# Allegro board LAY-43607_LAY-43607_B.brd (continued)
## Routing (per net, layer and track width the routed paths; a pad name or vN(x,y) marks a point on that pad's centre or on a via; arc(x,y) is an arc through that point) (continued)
IFC_AD6: length 65.4
  TOP w0.137: v2(84.82,50.41) 84.4,50.41 84.3,50.32 83.13,50.32 82.76,49.95 79.47,49.95 78.36,48.84 76.52,48.84 75.87,48.2 U14.A11
  L3_INT_1 w0.107: v2(84.82,50.41) 85.38,50.97 94.95,50.97 96.51,49.42 99.02,49.42 101.88,46.56 101.88,45.9 102.91,44.87 102.91,44.87 105.75,42.03 105.75,40.71 106.15,40.31 106.15,40.16 105.72,39.72 105.72,39.57 105.87,39.42 106.02,39.42 106.46,39.86 106.61,39.86 106.76,39.71 106.76,39.55 106.32,39.12 106.32,38.97 106.47,38.82 106.62,38.82 107.06,39.25 107.21,39.25 107.36,39.1 107.36,38.95 106.92,38.52 106.92,38.36 107.08,38.21 107.23,38.21 107.66,38.65 107.81,38.65 107.96,38.5 107.96,38.35 107.53,37.91 107.53,37.76 107.68,37.61 107.83,37.61 108.27,38.05 108.42,38.05 109.15,37.31 109.15,33.79 109.26,33.68 109.54,33.68 109.64,33.58 109.64,33.36 109.54,33.26 109.26,33.26 109.15,33.15 v2(109.15,32.34)
  BOTTOM w0.137: U522.J4 111.58,24.85 111.58,25.14 111.48,25.24 111.48,25.53 111.61,25.66 111.61,26.18 111.47,26.32 111.11,26.32 110.98,26.45 110.98,26.73 111.11,26.87 111.47,26.87 111.61,27 111.61,27.42 111.47,27.56 111.01,27.56 110.88,27.7 110.88,27.97 111.01,28.11 111.47,28.11 111.61,28.24 111.61,28.81 110.26,30.16 110.06,30.16 109.67,29.76 109.48,29.76 109.28,29.96 109.28,30.15 109.67,30.55 109.67,30.74 109.15,31.26 v2(109.15,32.34)
IFC_AD7: length 66.9
  TOP w0.137: v2(84.89,49.49) 84.79,49.39 84.24,49.39 84.21,49.36 79.68,49.36 78.51,48.19 77.01,48.19 75.77,46.96 75.06,46.96 U14.B12
  L3_INT_1 w0.107: v2(108.34,31.95) 108.34,32.48 108.51,32.65 108.51,33.04 108.51,33.04 108.51,34.03 108.51,34.03 108.51,35.71 103.77,40.46 103.77,41.27 103.24,41.8 103.19,41.8 102.61,42.37 102.46,42.37 101.75,41.66 101.6,41.66 101.45,41.81 101.45,41.96 102.16,42.67 102.16,42.82 102.01,42.98 101.86,42.98 101.15,42.26 101,42.27 100.85,42.42 100.85,42.57 101.56,43.28 101.56,43.43 101.41,43.58 101.26,43.58 100.54,42.87 100.39,42.87 100.24,43.02 100.24,43.17 100.95,43.88 100.95,44.03 100.7,44.29 100.7,44.75 100.59,44.86 99.96,44.86 99.85,44.97 99.85,45.18 99.96,45.29 100.59,45.29 100.7,45.39 100.7,45.61 100.59,45.71 99.96,45.71 99.85,45.82 99.85,46.03 99.96,46.14 100.59,46.14 100.7,46.25 100.7,46.65 98.46,48.89 96.23,48.89 95.49,49.62 93.41,49.62 92.53,50.5 86.47,50.5 85.46,49.49 v2(84.89,49.49)
  BOTTOM w0.137: U522.H4 110.63,24.17 110.07,24.17 109.81,24.43 109.81,26.28 109.36,26.73 109.06,26.73 108.54,27.26 108.54,27.56 107.96,28.14 107.96,31.57 v2(108.34,31.95)
IFC_AD8: length 81.9
  TOP w0.137: v2(105.04,3.18) S1.20 ; v2(84.36,49.85) 83.07,49.85 82.84,49.63 79.57,49.63 78.4,48.46 76.87,48.46 75.8,47.4 U14.A12
  L3_INT_1 w0.107: v2(84.36,49.85) 84.41,49.9 85.05,49.9 85.89,50.74 92.63,50.74 93.44,49.93 95.51,49.93 96.26,49.18 98.5,49.18 101.09,46.59 101.09,45.29 104.74,41.64 104.74,39.92 108.75,35.91 108.75,32.94 108.75,32.94 108.75,32.17 109.94,30.98 110.32,30.98 112.04,29.26 112.04,23.91 111.05,22.92 111.05,7.37 106.88,3.2 105.46,3.2 105.45,3.18 v2(105.04,3.18)
IFC_AD9: length 82.1
  TOP w0.137: v2(84.41,48.97) 83.12,48.97 82.54,48.39 80.65,48.39 80.64,48.38 79.07,48.38 78.62,47.93 77.23,47.93 75.9,46.6 U14.A13 ; S1.19 v2(105.04,4.45)
  L3_INT_1 w0.107: v2(84.41,48.97) 85.54,48.97 86.78,50.21 92.5,50.21 93.39,49.32 95.44,49.32 96.1,48.65 98.14,48.65 99.13,47.66 99.13,43.55 102.18,40.5 103.39,40.5 108.28,35.62 108.28,33.93 108.28,33.93 108.28,33.14 108.28,32.8 107.93,32.45 107.93,30.48 108.29,30.12 110.85,30.12 111.8,29.16 111.8,24.11 110.83,23.13 110.83,18.69 108.77,16.63 108.77,6.38 106.84,4.45 v2(105.04,4.45)
IFC_AD10: length 81.5
  TOP w0.137: U14.B14 74.99,46.16 75.98,46.16 77.28,47.46 81.98,47.46 82.66,48.14 84.08,48.14 84.49,48.55 84.59,48.55 84.61,48.56 v2(85.23,48.56) ; S1.18 v2(105.04,5.72)
  L3_INT_1 w0.107: v2(85.23,48.56) 86.38,48.56 87.08,49.27 87.49,49.27 87.68,49.08 93.36,49.08 93.65,48.8 93.71,48.8 94.43,48.07 98.16,48.07 98.83,47.4 98.83,43.43 102.01,40.25 103.31,40.25 103.59,39.97 103.59,39.26 106.26,36.6 106.87,36.6 108.04,35.42 108.04,33.83 108.04,32.99 107.7,32.65 107.7,30.13 108.04,29.79 110.75,29.79 111.52,29.01 111.52,24.3 110.55,23.33 110.55,18.84 108.54,16.83 108.54,6.82 107.44,5.72 v2(105.04,5.72)
IFC_AD11: length 77.7
  TOP w0.137: v2(84.67,48.12) 84.37,47.82 82.72,47.82 82.09,47.2 77.51,47.2 76.11,45.8 U14.A14 ; S1.17 v2(105.04,6.99)
  L3_INT_1 w0.107: v2(84.67,48.12) 86.9,48.12 87.1,48.33 90.84,48.33 91.03,48.13 91.39,48.13 91.82,48.56 93.61,48.56 94.33,47.84 97.38,47.84 97.48,47.73 97.48,44.2 101.3,40.38 101.41,40.38 101.69,40.1 101.69,39.99 102.83,38.86 103.61,38.86 106.18,36.29 106.18,35.91 106.66,35.43 107,35.43 107.81,34.61 107.81,33.74 107.81,33.73 107.81,33.33 107.81,33.33 107.81,33.09 107.46,32.74 107.46,30.04 108.04,29.46 110.67,29.46 111.26,28.87 111.26,24.36 110.33,23.43 110.33,19.28 107.81,16.76 107.81,7.45 107.35,6.99 v2(105.04,6.99)
IFC_AD12: length 62.3
  TOP w0.137: v2(93.81,42.99) 93.18,43.61 85.63,43.61 85.24,43.99 82.72,43.99 82.37,43.64 77.35,43.64 76.4,44.6 75.02,44.6 U14.B15 ; S1.16 v2(106.1,8.27)
  L4_INT_2 w0.107: v2(93.81,42.99) 93.81,40.37 95.22,38.96 95.22,35.35 96.09,34.48 96.26,34.48 104.11,26.63 104.11,10.26 v2(106.1,8.27)
IFC_AD13: length 60.5
  TOP w0.137: U14.A15 76.7,45 77.13,44.57 81.25,44.57 81.53,44.29 85.34,44.29 85.67,43.96 93.74,43.96 v2(94.24,43.45) ; S1.15 v2(105.57,9.54)
  L4_INT_2 w0.107: v2(105.57,9.54) 104.38,10.73 104.38,27.65 97.32,34.71 96.19,34.71 95.48,35.42 95.48,39.11 94.04,40.54 94.04,41.85 94.24,42.05 v2(94.24,43.45)
IFC_AD14: length 58
  TOP w0.137: U14.A16 75.99,44.2 76.84,43.35 82.45,43.35 82.72,43.61 85.25,43.61 85.52,43.35 91.33,43.35 93.01,41.67 v2(94.65,41.67) ; S1.14 v2(105.53,10.81)
  L4_INT_2 w0.107: v2(94.65,41.67) 94.65,40.39 94.99,40.05 94.99,40.03 95.71,39.31 95.71,35.57 96.29,34.99 97.38,34.99 104.63,27.74 104.63,11.71 v2(105.53,10.81)
IFC_AD15: length 56.3
  TOP w0.137: S1.13 v2(105.53,12.08) ; v2(95.23,40.89) 93.05,40.89 90.89,43.04 85.07,43.04 84.79,43.32 82.97,43.32 82.7,43.05 76.14,43.05 75.8,43.4 U14.A17
  L4_INT_2 w0.107: v2(95.23,40.89) 95.23,40.13 95.95,39.41 95.95,35.7 96.43,35.22 97.48,35.22 104.93,27.77 104.93,12.68 v2(105.53,12.08)
IFC_AVD: length 65.7
  TOP w0.137: U14.A18 v3(75.99,42.6)
  L3_INT_1 w0.107: v3(107.46,25) 107.9,24.56 107.9,23.02 108.44,22.49 108.61,22.49 108.75,22.63 108.75,24.45 107.46,25.74 107.46,25.8 106.24,27.01 105.24,27.01 104.24,26.01 104.04,26.01 103.85,26.21 103.85,27.25 103.95,27.36 105.09,27.36 105.2,27.46 105.2,27.68 105.09,27.78 103.95,27.78 103.85,27.89 103.85,28.52 103.5,28.87 103.5,29.02 103.67,29.18 103.67,29.34 103.52,29.49 103.37,29.49 103.2,29.32 103.05,29.32 102.9,29.47 102.9,29.62 103.06,29.79 103.06,29.94 102.91,30.09 102.76,30.09 102.6,29.92 102.44,29.92 102.29,30.07 102.29,30.23 102.46,30.39 102.46,30.54 102.31,30.69 102.16,30.69 101.99,30.53 101.84,30.53 101.69,30.68 101.69,30.83 101.86,31 101.86,31.15 101.71,31.3 101.56,31.3 101.39,31.13 101.24,31.13 101.08,31.28 100.8,31.28 98.92,33.16 97.81,33.16 97.12,33.85 93.69,33.85 93.18,34.36 93.03,34.36 92.55,33.89 92.4,33.89 92.25,34.04 92.25,34.19 92.73,34.66 92.73,34.81 92.58,34.96 92.43,34.96 91.95,34.49 91.8,34.49 91.65,34.64 91.65,34.79 92.12,35.27 92.12,35.42 91.97,35.57 91.82,35.57 91.35,35.09 91.2,35.09 91.05,35.24 91.05,35.4 91.52,35.87 91.52,36.02 91.37,36.17 91.22,36.17 90.74,35.7 90.59,35.7 90.44,35.85 90.44,36 90.92,36.47 90.92,36.62 90.77,36.78 90.61,36.78 90.14,36.3 89.99,36.3 89.84,36.45 89.84,36.6 90.31,37.08 90.31,37.23 90.16,37.38 90.01,37.38 89.54,36.9 89.39,36.9 89.24,37.06 89.24,37.21 89.71,37.68 89.71,37.83 88.43,39.11 88.28,39.11 88.01,38.83 87.86,38.83 87.71,38.98 87.71,39.14 87.96,39.39 87.96,39.58 87.68,39.86 86.79,39.86 86.65,40 86.65,40.48 86.55,40.59 84.13,40.59 83.12,41.6 v2(82,41.6) 81.33,42.27 81.09,42.27 80.99,42.37 80.99,42.59 80.88,42.7 80.67,42.7 80.56,42.59 80.56,42.37 80.45,42.27 79.63,42.27 79.3,42.6 v3(75.99,42.6)
  BOTTOM w0.137: R873.1 82.02,41.62 v2(82,41.6) ; U522.C4 v3(107.46,25)
IFC_CLE: length 78.1
  TOP w0.137: S1.12 v2(105.52,13.35) ; U14.C19 v3(73.42,41.4)
  L3_INT_1 w0.107: v3(73.42,41.4) 73.37,41.34 73.22,41.34 73.06,41.5 73.06,41.65 73.18,41.78 74.48,41.78 74.76,41.5 75.01,41.5 75.12,41.6 75.12,41.7 75.22,41.81 75.44,41.81 75.54,41.7 75.54,41.6 75.65,41.5 75.86,41.5 75.97,41.6 75.97,41.7 76.08,41.81 76.29,41.81 76.4,41.7 76.4,41.6 76.5,41.5 76.72,41.5 76.82,41.6 76.82,41.7 76.93,41.81 77.14,41.81 77.25,41.7 77.25,41.6 77.36,41.5 77.57,41.5 77.68,41.6 77.68,41.7 77.78,41.81 78,41.81 78.1,41.7 78.1,41.6 78.21,41.5 78.76,41.5 79.93,40.33 81.64,40.33 81.73,40.42 83.11,40.42 84.23,39.29 84.89,39.29 85.05,39.13 85.21,39.13 85.63,39.56 85.79,39.56 85.94,39.41 85.94,39.26 85.51,38.83 85.51,38.68 86.45,37.73 86.6,37.73 87.01,38.13 87.16,38.13 87.31,37.98 87.31,37.83 86.9,37.43 86.9,37.28 87.06,37.13 87.21,37.13 87.61,37.53 87.76,37.53 87.91,37.38 87.91,37.23 87.51,36.83 87.51,36.68 87.66,36.52 87.81,36.52 88.21,36.93 88.36,36.93 88.51,36.78 88.51,36.63 88.11,36.22 88.11,36.07 88.26,35.92 88.41,35.92 88.82,36.32 88.97,36.32 89.12,36.17 89.12,36.02 88.71,35.62 88.71,35.47 89.69,34.49 89.84,34.49 90.27,34.92 90.42,34.92 90.57,34.77 90.57,34.62 90.14,34.19 90.14,34.04 90.29,33.89 90.44,33.89 90.87,34.32 91.02,34.32 91.17,34.17 91.17,34.02 90.74,33.59 90.74,33.44 90.9,33.29 91.05,33.29 91.48,33.72 91.63,33.72 91.78,33.57 91.78,33.42 91.35,32.99 91.35,32.83 92.01,32.17 94.89,32.17 96.28,30.79 100.42,30.79 102.3,28.91 102.3,24.96 104.52,22.74 104.98,22.74 105.33,23.09 105.33,24.37 105.43,24.48 105.72,24.48 105.86,24.61 105.86,24.77 105.72,24.9 105.43,24.9 105.33,25.01 105.33,26.02 105.47,26.17 106.14,26.17 106.38,25.93 106.56,25.93 106.82,25.67 106.82,24.1 v3(107.49,23.43) 107.23,23.18 106.94,23.18 106.83,23.07 106.63,23.07 106.04,22.48 106.04,21.1 106.82,20.32 106.82,17.18 105.52,15.88 v2(105.52,13.35)
  BOTTOM w0.137: U522.D5 v3(107.49,23.43)
IFC_OE_B: length 66.9
  TOP w0.137: U14.C18 v3(74.22,42.2)
  L3_INT_1 w0.107: v3(107.39,24.14) 107.1,24.43 107.1,25.84 106.73,26.22 106.47,26.22 106.15,26.54 105.32,26.54 104.91,26.13 104.91,25.89 104.8,25.78 104.44,25.78 104.33,25.67 104.33,25.46 104.44,25.35 104.8,25.35 104.91,25.25 104.91,23.9 104.61,23.6 104.32,23.6 103.9,24.03 103.9,24.18 104.24,24.52 104.24,24.67 104.09,24.82 103.94,24.82 103.6,24.48 103.45,24.48 103.3,24.63 103.3,24.78 103.64,25.12 103.64,25.27 103.49,25.43 103.34,25.43 103,25.08 102.85,25.08 102.66,25.27 102.66,26.25 102.77,26.35 103.27,26.35 103.38,26.46 103.38,26.67 103.27,26.78 102.77,26.78 102.66,26.89 102.66,27.1 102.77,27.21 103.27,27.21 103.38,27.31 103.38,27.53 103.27,27.63 102.77,27.63 102.66,27.74 102.66,27.95 102.77,28.06 103.27,28.06 103.38,28.17 103.38,28.38 103.27,28.49 102.77,28.49 102.66,28.59 102.66,28.98 100.55,31.1 97.29,31.1 97.17,31.21 97.17,32.07 97.28,32.18 98.82,32.18 98.93,32.28 98.93,32.5 98.82,32.6 97.28,32.6 97.17,32.71 97.17,33.21 97.06,33.32 96.14,33.32 96.03,33.21 96.03,32.59 95.93,32.48 95.71,32.48 95.61,32.59 95.61,33.21 95.5,33.32 95.29,33.32 95.18,33.21 95.18,32.59 95.07,32.48 94.86,32.48 94.75,32.59 94.75,33.21 94.65,33.32 94.43,33.32 94.33,33.21 94.33,32.59 94.22,32.48 94.01,32.48 93.9,32.59 93.9,33.21 93.79,33.32 93.58,33.32 93.47,33.21 93.47,32.59 93.37,32.48 93.15,32.48 93.05,32.59 93.05,33.21 92.94,33.32 92.46,33.32 85.53,40.25 83.81,40.25 83.32,40.74 v2(81.47,40.74) 80.04,40.74 78.58,42.2 v3(74.22,42.2)
  BOTTOM w0.137: R203.2 v2(81.47,40.74) ; U522.D4 v3(107.39,24.14)
IFC_RB0_B: length 64.5
  TOP w0.137: v2(84.89,35.1) 85.54,35.74 85.54,37.82 82.2,41.16 81.36,41.16 v2(80.93,41.59) ; U14.C16 v3(73.42,43.8)
  BOTTOM w0.137: v2(84.89,35.1) 86.21,33.78 86.21,32.46 87.59,31.08 89.73,31.08 95.37,25.43 95.37,24.58 98.57,21.39 98.83,21.39 98.97,21.25 98.97,19.51 99.1,19.37 99.38,19.37 99.52,19.51 99.52,21.25 99.65,21.39 99.93,21.39 100.06,21.25 100.06,19.51 100.2,19.37 100.48,19.37 100.61,19.51 100.61,21.25 100.75,21.39 101.02,21.39 101.16,21.25 101.16,19.51 101.3,19.37 101.57,19.37 101.71,19.51 101.71,21.25 101.85,21.39 102.12,21.39 102.26,21.25 102.26,19.51 102.4,19.37 102.67,19.37 102.81,19.51 102.81,21.25 102.94,21.39 U522.C8 ; v3(73.42,43.8) 73.8,43.42 75.86,43.42 76.82,42.46 80.07,42.46 v2(80.93,41.59) 82.1,42.76 R204.2
IFC_RB1_B: length 11.9
  TOP w0.137: U14.D16 v3(72.62,43.8)
  BOTTOM w0.137: v3(72.62,43.8) 73.03,44.2 75.68,44.2 76.9,42.98 81.81,42.98 82.24,43.41 82.56,43.41 R205.2
IFC_TE: length 11.5
  TOP w0.137: v3(72.63,46.19) 72.62,46.19 U14.E14
  BOTTOM w0.137: R814.1 82.1,45.81 82.06,45.77 81.71,45.77 81.13,46.35 75.03,46.35 74.5,45.82 73,45.82 v3(72.63,46.19)
IFC_WE_B: length 76.2
  TOP w0.137: U14.C15 v3(74.22,44.6) ; S1.11 v2(106.08,14.62)
  L3_INT_1 w0.107: v2(106.08,14.62) 106.08,15.88 107.37,17.17 107.37,20.2 107.41,20.25 v3(107.41,22.56) 107.79,22.19 107.79,18.18 108,17.96 108.29,17.96 109.42,19.09 109.42,19.41 109.53,19.51 110,19.51 110.11,19.62 110.11,19.83 110,19.94 109.53,19.94 109.42,20.05 109.42,20.26 109.53,20.37 110,20.37 110.11,20.47 110.11,20.69 110,20.79 109.53,20.79 109.42,20.9 109.42,21.11 109.53,21.22 110,21.22 110.11,21.33 110.11,21.54 110,21.65 109.53,21.65 109.42,21.75 109.42,21.97 109.53,22.07 110,22.07 110.11,22.18 110.11,22.39 110,22.5 109.53,22.5 109.42,22.61 109.42,24.71 108.63,25.5 108.63,26.36 108.34,26.65 107.42,26.65 101.84,32.22 100.77,32.22 99.07,33.93 98.4,33.93 97.11,35.22 93.93,35.22 92.2,36.94 92.2,38.62 92.75,39.16 92.75,40.24 92,40.99 90.71,40.99 89.82,41.88 87.1,41.88 86.75,42.23 84.1,42.23 81.98,44.35 81.98,45.02 81.64,45.37 81.34,45.37 81.21,45.24 80.8,45.24 80.16,44.6 v3(74.22,44.6)
  BOTTOM w0.137: v3(107.41,22.56) U522.C7
IFC_WP_B: length 65
  TOP w0.137: U14.D19 v3(72.62,41.4)
  L3_INT_1 w0.107: v3(106.44,25.39) 106.44,24.16 106.28,24.01 106.28,23.03 106.17,22.92 105.91,22.92 105.72,22.74 105.72,20.28 105.61,20.18 105.14,20.18 105.01,20.31 105.01,21.71 101.95,24.76 101.95,28.62 100.13,30.44 96.12,30.44 94.8,31.76 91.97,31.76 91.51,32.23 91.36,32.23 91.16,32.03 91.01,32.03 90.86,32.19 90.86,32.34 91.05,32.53 91.05,32.68 90.9,32.83 90.75,32.83 90.56,32.64 90.41,32.64 90.26,32.79 90.26,32.94 90.45,33.13 90.45,33.28 90.3,33.43 90.15,33.43 89.96,33.24 89.8,33.24 89.65,33.39 89.65,33.54 89.85,33.74 89.85,33.89 89.7,34.04 89.54,34.04 89.35,33.84 89.2,33.84 89.05,34 89.05,34.15 89.24,34.34 89.24,34.49 89.09,34.64 88.94,34.64 88.75,34.45 88.6,34.45 88.45,34.6 88.45,34.75 88.64,34.94 88.64,35.09 88.49,35.25 88.34,35.25 88.14,35.05 87.99,35.05 87.84,35.2 87.84,35.35 88.04,35.55 88.04,35.7 87.89,35.85 87.73,35.85 87.54,35.66 87.39,35.66 87.24,35.81 87.24,35.96 87.43,36.15 87.43,36.3 84.85,38.88 84.15,38.88 83.71,39.33 83.2,39.33 83.1,39.43 83.1,39.73 82.99,39.84 82.78,39.84 82.67,39.73 82.67,39.43 82.56,39.33 81.28,39.33 81.18,39.43 81.18,39.83 81.07,39.94 80.86,39.94 80.75,39.83 80.75,39.43 80.64,39.33 80.43,39.33 80.32,39.43 80.32,39.83 80.22,39.94 80,39.94 79.9,39.83 79.9,39.43 79.79,39.33 77.25,39.33 77.09,39.49 77.09,39.64 77.25,39.81 79.26,39.81 79.36,39.91 79.36,40.26 78.67,40.96 77.4,40.96 77.29,41.07 77.29,41.08 77.18,41.19 76.97,41.19 76.86,41.08 76.86,41.07 76.76,40.96 76.54,40.96 76.44,41.07 76.44,41.08 76.33,41.19 76.12,41.19 76.01,41.08 76.01,41.07 75.9,40.96 75.69,40.96 75.58,41.07 75.58,41.08 75.48,41.19 75.26,41.19 75.16,41.08 75.16,41.07 75.05,40.96 73.26,40.96 72.83,41.4 v3(72.62,41.4)
  BOTTOM w0.137: U522.C3 v3(106.44,25.39)
INA_VDD_S_N: length 2.6
  TOP w0.254: R889.2 123.81,55.01 C1335.2 124.83,55.01 125.33,54.51 U558.9
INA_VDD_S_P: length 2.3
  TOP w0.254: R888.1 C1335.1 124.83,53.99 124.84,54.01 U558.10
IRQ_RTC_B: length 68.9
  TOP w0.137: R742.1 27.42,76.47 27.43,76.47 v2(28.46,76.47) ; U14.J5 69.42,53.39 v3(69.43,53.39)
  L3_INT_1 w0.107: v2(72.7,68.29) 72.22,67.81 68.41,67.81 67.97,68.25 64.86,68.25 64.61,68 62.14,68 61.95,68.19 58.86,68.19 56.62,70.43 52.15,70.43 51.38,71.21 44.06,71.21 43.53,71.73 39.44,71.73 38.94,71.23 38.03,71.23 37.53,71.74 36.13,71.74 35.53,72.33 34.64,72.33 30.5,76.47 v2(28.46,76.47)
  BOTTOM w0.137: v3(69.43,53.39) 69.05,53.77 69.05,55.17 69.5,55.62 69.5,56.2 71.42,58.12 71.42,67.01 v2(72.7,68.29) ; U523.17 v2(28.46,76.47)
LED_ASLEEP: length 6.3
  TOP w0.137: D2.C 95.25,53.61 95.25,48.32 R191.2
LP_TMP_DETECT_B: length 14.2
  TOP w0.137: R560.1 77.56,55.85 v2(77.58,55.83)
  TOP w0.381: v3(70.23,47.79) 69.83,47.4 U14.H12
  BOTTOM w0.137: v2(77.58,55.83) 77.58,55.34 74.41,52.17 72.47,52.17 72.25,51.95 72.25,51.69 71.98,51.42 70.77,51.42 70.63,51.28 70.63,48.2 v3(70.23,47.79)
LS1043A_GND_SENSE: length 104.9
  TOP w0.137: v2(60.62,53.39) U14.W5
  TOP w0.254: v2(129.44,37.76) 129.7,38.02 129.7,38.7 129.33,39.06 126.5,39.06 125.51,40.04 124.71,40.04 v2(124.52,39.85)
  L3_INT_1 w0.254: v2(62.94,57.8) 63.28,57.46 63.5,57.46 64.17,56.8 73.71,56.8 74.01,57.1 74.48,57.1 78.33,60.95 84.02,60.95 84.45,60.52 85.99,60.52 86.61,61.14 87.81,61.14 88.16,61.49 90.73,61.49 91.38,60.84 92.46,60.84 93.56,59.75 94.29,59.75 95.38,58.66 101.59,58.66 102.62,57.64 107.47,57.64 109.35,55.76 114.14,55.76 115.66,54.24 117.15,54.24 v4(117.48,53.9)
  L4_INT_2 w0.254: v4(117.48,53.9) 117.88,53.85 118.18,54.09 118.67,54.03 118.95,53.75 118.95,53.31 118.69,53.06 118.09,53.06 117.18,52.15 117.18,51.19 114.98,48.99 114.98,42.71 116.51,41.18 117.02,41.18 117.83,40.38 117.83,38.36 118.36,37.83 121.5,37.83 123.68,40.01 123.9,40.01 124.06,39.84 v2(124.52,39.85)
  BOTTOM w0.137: v2(62.94,57.8) 62.94,57.38 63.3,57.02 63.3,54.96 63.45,54.81 63.45,53.89 63.36,53.79 62.86,53.79 62.63,53.56 62.63,53.07 62.55,53 61.02,53 v2(60.62,53.4)
  BOTTOM w0.254: R897.2 129.64,38.32 129.64,37.96 v2(129.44,37.76)
LS1043A_VDD_SENSE: length 104.2
  TOP w0.137: v2(61.42,53.4) U14.V5
  TOP w0.254: v2(124.51,40.57) 124.65,40.43 125.67,40.43 126.65,39.44 129.49,39.44 130.08,38.85 130.08,38.02 v2(130.34,37.76)
  L3_INT_1 w0.254: v2(62.47,58.33) 63.21,58.33 64.37,57.18 73.55,57.18 73.86,57.48 74.29,57.48 78.15,61.35 84.16,61.35 84.61,60.9 85.84,60.9 86.45,61.52 87.65,61.52 88.01,61.87 90.89,61.87 91.54,61.23 92.62,61.23 93.71,60.13 94.45,60.13 95.54,59.04 101.75,59.04 102.77,58.02 107.63,58.02 109.51,56.14 114.29,56.14 115.82,54.62 117.39,54.62 v4(117.59,54.82)
  L4_INT_2 w0.254: v2(124.51,40.57) 124.05,40.56 123.89,40.39 123.52,40.39 121.35,38.21 118.52,38.21 118.21,38.52 118.21,40.53 117.18,41.56 116.67,41.56 115.36,42.87 115.36,48.83 117.56,51.03 117.56,51.99 118.24,52.67 118.85,52.67 119.33,53.15 119.33,53.91 118.85,54.39 118.23,54.47 117.99,54.77 v4(117.59,54.82)
  BOTTOM w0.137: v2(61.42,53.4) 61.82,53.79 61.82,54.41 61.84,54.42 61.84,54.43 61.94,54.54 61.95,54.54 62.01,54.6 62.59,54.6 62.7,54.71 62.7,56.65 62.47,56.88 62.47,58.21 62.47,58.22 v2(62.47,58.33)
  BOTTOM w0.254: v2(130.34,37.76) 130.12,37.97 130.12,38.33 R893.2
LS1046A_GND_SENSE: length 91.9
  TOP w0.137: v3(71.02,40.6) U14.G20
  TOP w0.254: v2(128.37,27.23) 128.1,26.97 128.1,25.79 127.95,25.63 127.95,21.38 126.9,20.34 122.53,20.34 120.78,22.09 117.14,22.09 114.54,19.48 107.58,19.48 106.9,18.81 106.52,18.33 106.55,18 v2(106.31,17.7)
  L3_INT_1 w0.107: 75.93,39.44 75.89,39.46 75.86,39.62 75.75,39.69 75.22,40.23 71.39,40.23 v3(71.02,40.6)
  L3_INT_1 w0.254: v2(106.31,17.7) 106.31,18.45 104.3,20.46 104.3,21.4 100.65,25.06 100.65,29.23 99.84,30.03 95.9,30.03 94.59,31.35 91.01,31.35 85.66,36.7 85.66,37.42 84.77,38.31 83.54,38.31 83.02,38.84 76.62,38.84 76.18,39.28 75.93,39.44
  BOTTOM w0.254: v2(128.37,27.23) 128.1,27.49 128.1,29.11 128.53,29.54 128.53,35.47 128.27,35.73 128.27,38.3 R898.2
LS1046A_VDD_SENSE: length 92.4
  TOP w0.137: v3(70.22,41.4) U14.G19
  TOP w0.254: v2(105.65,18.23) 105.89,18.53 106.22,18.57 106.62,19.06 107.42,19.86 114.38,19.86 116.99,22.47 120.93,22.47 122.69,20.72 126.75,20.72 127.57,21.54 127.57,25.79 127.72,25.94 127.72,26.97 v2(127.46,27.23)
  L3_INT_1 w0.107: 75.72,39.12 75.69,39.14 75.52,39.1 75.42,39.16 75.22,39.37 70.94,39.37 70.67,39.65 70.67,40.66 70.22,41.1 v3(70.22,41.4)
  L3_INT_1 w0.254: 75.72,39.12 75.94,38.98 76.46,38.45 82.86,38.45 83.38,37.93 84.61,37.93 85.28,37.26 85.28,36.55 90.85,30.97 94.43,30.97 95.75,29.65 99.69,29.65 100.26,29.07 100.26,24.76 103.89,21.14 103.89,19.99 v2(105.65,18.23)
  BOTTOM w0.254: R895.2 127.89,38.3 127.89,35.57 128.15,35.32 128.15,29.69 127.72,29.26 127.72,27.49 v2(127.46,27.23)
M2_1_REFCLK_EN#: length 19.6
  TOP w0.137: v4(21.88,49.98) 21.91,50.01 R798.1 ; U50.19 21.29,63.34 R775.2 20.21,62.27 20.21,61.29 v2(20.77,60.73)
  L3_INT_1 w0.107: v2(20.77,60.73) 20.77,59.85 18.88,57.95 18.88,52.98 v4(21.88,49.98)
M2_1_REFCLK_N: length 20.1
  TOP w0.124: v2(29.95,58.82) 29.66,59.11 29.18,59.11 R788.2
  L3_INT_1 w0.094: v2(21.43,52.8) 21.64,53.01 21.64,55.77 21.43,55.98 21.43,57.37 22.54,58.48 26.01,58.48 26.55,57.94 28.72,57.94 28.81,58.03 28.81,58.12 28.9,58.22 29.09,58.22 29.19,58.12 29.19,58.03 29.28,57.94 29.47,57.94 29.56,58.03 29.56,58.12 29.66,58.22 29.84,58.22 29.94,58.12 29.94,58.03 30.03,57.94 30.4,57.94 30.66,58.2 30.66,58.78 30.36,59.09 30.22,59.09 v2(29.95,58.82)
  BOTTOM w0.124: J46.49 21.63,53 v2(21.43,52.8)
M2_1_REFCLK_P: length 20.1
  TOP w0.124: R787.2 29.18,59.43 29.66,59.43 v2(29.95,59.73)
  L3_INT_1 w0.094: v2(22.26,52.8) 22.01,53.04 22.01,55.92 21.8,56.13 21.8,57.22 22.69,58.11 25.86,58.11 26.39,57.57 30.56,57.57 31.03,58.04 31.03,58.94 30.51,59.46 30.22,59.46 v2(29.95,59.73)
  BOTTOM w0.124: J46.47 22.13,52.92 v2(22.26,52.8)
M2_2_REFCLK_EN#: length 40.5
  TOP w0.137: v2(22.75,60.78) 22.75,61.88 R776.2 21.92,62.83 21.94,62.84 U50.20 ; R806.1 37.66,40 37.52,40.14 v2(37.42,40.14)
  L3_INT_1 w0.107: v2(37.42,40.14) 39.44,42.15 39.44,53.06 30.96,61.54 30.6,61.54 30.05,62.08 25.14,62.08 24.02,60.96 22.93,60.96 v2(22.75,60.78)
M2_2_REFCLK_N: length 34.4
  TOP w0.124: R786.2 34.13,63.92 34.77,63.92 34.9,63.8 34.9,63.69 35.02,63.57 35.27,63.57 35.39,63.69 35.39,63.8 35.52,63.92 37.01,63.92 37.84,63.1 37.84,59.74 37.43,59.34 32.45,59.34 v2(32.15,59.63) ; v2(27.53,43.63) 27.39,43.5 J52.49
  L3_INT_1 w0.094: v2(32.15,59.63) 32.42,59.36 32.71,59.36 33.02,59.05 33.02,58.05 28.2,53.23 28.2,44.78 27.36,43.94 27.36,43.8 v2(27.53,43.63)
M2_2_REFCLK_P: length 34.4
  TOP w0.124: J52.47 26.89,43.55 v2(26.82,43.62) ; v2(32.15,58.72) 32.45,59.02 37.57,59.02 38.16,59.61 38.16,63.23 37.15,64.24 34.13,64.24 R785.2
  L3_INT_1 w0.094: v2(32.15,58.72) 32.42,58.99 32.55,58.99 32.65,58.9 32.65,58.2 27.83,53.39 27.83,44.94 26.99,44.09 26.99,43.79 v2(26.82,43.62)
MR_B: length 4.3
  TOP w0.137: v2(118.32,18.28) 118.32,18.7 118.33,18.71 U54.C1 117.65,19.2 117.64,19.19 R302.2
  BOTTOM w0.137: v2(118.32,18.28) 119.06,18.28 119.66,18.88 U534.4
NAND_CS_B: length 66.7
  TOP w0.137: v3(106.64,22.57) 105.89,22.57 105.83,22.62 R737.2 ; U14.C17 v3(74.22,43)
  L3_INT_1 w0.107: v3(106.64,22.57) 106.91,22.84 106.92,22.84 107.03,22.95 107.53,22.95 108.17,22.31 108.17,18.78 108.31,18.64 108.58,18.64 108.69,18.74 108.69,19.17 108.79,19.28 108.89,19.28 109,19.38 109,19.6 108.89,19.7 108.79,19.7 108.69,19.81 108.69,20.02 108.79,20.13 108.89,20.13 109,20.24 109,20.45 108.89,20.56 108.79,20.56 108.69,20.66 108.69,21.6 108.67,21.62 108.67,21.92 108.97,22.23 108.97,24.59 101.96,31.61 100.9,31.61 98.98,33.53 98.02,33.53 97.13,34.43 96.73,34.43 96.63,34.53 96.63,34.71 96.52,34.81 96.31,34.81 96.2,34.71 96.2,34.53 96.09,34.43 95.88,34.43 95.77,34.53 95.77,34.71 95.67,34.81 95.45,34.81 95.35,34.71 95.35,34.53 95.24,34.43 95.03,34.43 94.92,34.53 94.92,34.71 94.81,34.81 94.6,34.81 94.49,34.71 94.49,34.53 94.39,34.43 93.91,34.43 93.55,34.79 93.55,34.94 93.57,34.97 93.57,35.12 93.42,35.27 93.27,35.27 93.25,35.24 93.1,35.24 92.94,35.39 92.94,35.54 92.97,35.57 92.97,35.72 92.82,35.87 92.67,35.87 92.64,35.85 92.49,35.85 92.34,36 92.34,36.15 92.37,36.17 92.37,36.32 92.22,36.48 92.06,36.48 92.04,36.45 91.89,36.45 91.74,36.6 91.74,36.75 91.76,36.78 91.76,36.93 91.61,37.08 91.46,37.08 91.44,37.05 91.28,37.05 90.84,37.49 90.84,37.64 91.53,38.33 91.53,38.48 91.38,38.64 91.23,38.64 90.54,37.95 90.39,37.95 89.28,39.06 89.28,39.21 89.83,39.75 89.83,39.9 89.68,40.05 89.52,40.05 88.98,39.51 88.83,39.51 87.33,41.01 86.53,41.01 86.13,41.41 85.89,41.41 85.79,41.3 85.79,41.01 85.68,40.9 85.47,40.9 85.36,41.01 85.36,41.3 85.25,41.41 83.77,41.41 83.16,42.01 82.45,42.01 81.46,43.01 79.57,43.01 79.56,43 78.96,43 78.85,43.1 78.85,43.17 78.75,43.28 78.53,43.28 78.43,43.17 78.43,43.1 78.32,43 78.11,43 78,43.1 78,43.17 77.89,43.28 77.68,43.28 77.57,43.17 77.57,43.1 77.47,43 77.25,43 77.15,43.1 77.15,43.17 77.04,43.28 76.83,43.28 76.72,43.17 76.72,43.1 76.61,43 76.4,43 76.29,43.1 76.29,43.17 76.19,43.28 75.97,43.28 75.87,43.17 75.87,43.1 75.76,43 75.55,43 75.44,43.1 75.44,43.17 75.33,43.28 75.12,43.28 75.01,43.17 75.01,43.1 74.91,43 v3(74.22,43)
  BOTTOM w0.137: v3(106.64,22.57) 106.64,22.58 U522.C6
OUT6_OE_B: length 7
  TOP w0.137: U50.31 30,62.84 30.71,63.56 30.71,64.03 31.79,65.1 33.52,65.1 33.7,65.28 R945.2
OVDD: length 109.3
  TOP w0.254: U561.2 66.5,80.26 66.15,80.61 v4(66.15,81.2) ; U37.1 75.69,98.32 75.47,98.54 v2(75.47,98.65) ; U539.8 80.19,98.33 v2(80.45,98.6) ; v2(74.62,98.61) 74.39,98.39 U35.8 ; U540.8 86.28,98.36 v2(86.55,98.62)
  TOP w0.305: v2(83.58,98.62) 83.28,98.33 U36.8 ; v2(86.04,112.36) 86.09,112.36 86.32,112.14 86.37,112.14 86.37,112.13 U548.6 U548.3
  TOP w0.381: v2(86.04,112.36) C1317.1 ; C1314.1 43.22,62.5 v4(42.63,61.92) ; v4(115.5,23.48) R810.1 ; v4(119.05,24.36) C492.1 120.13,25.11 U56.5 ; R737.1 104.07,22.67 104.73,23.33 v4(105.82,23.33) ; R868.1 v4(47.17,62.52) ; R302.1 v4(115.3,19.19) ; v4(99.45,73.68) C1328.1 ; U549.8 101.19,64.82 v4(101.05,64.97) ; C489.1 v4(121.54,17.83) 122.03,17.34 R298.1 ; U14.J18 69.02,42.6 v1(69.42,42.2) ; v1(69.42,44.6) 69.02,45 U14.J15 ; v1(69.42,43.8) 69.02,44.2 U14.J16 ; R947.1 v4(94.73,69.66) ; v1(69.42,43) 69.02,43.4 U14.J17 ; U14.G8 70.63,50.6 v1(71.03,50.99) ; R305.1 v4(117.08,27.53) ; R301.1 v4(119.87,20.87) ; U14.J14 69.03,45.8 v1(69.43,46.19) ; C1248.1 v3(112.25,22.57) ; U14.R7 v1(63.83,51.79)
  TOP w0.508: R819.2 v4(49.79,61.94) ; R171.1 v4(88.05,44.79) ; R172.1 v4(84.69,45.81) ; C498.1 v4(46.8,64.23) 46.8,64.23 R867.1 ; U532.2 v4(104.58,31.79) ; R355.1 v4(15.28,79.77) ; R824.2 v5(53.45,63.39)
  L4_INT_2 w0.889: 97.19,65.9 J74.1 96.65,66.07 ; 94.35,38.07 J11.2 94.35,36.64
  L5_PWR w0.889: 97.19,65.9 J74.1 96.48,66.62
  BOTTOM w0.203: v3(110.65,25) 110.63,25.02 110.63,25.69 110.6,25.72
  BOTTOM w0.305: C1308.1 86.39,98.47 v2(86.55,98.62) ; v2(74.62,98.61) 74.45,98.44 C449.1 ; v2(80.45,98.6) 80.37,98.52 C1306.1 ; R859.1 v2(85.3,95.57) 86.12,95.57 86.19,95.65 R860.1 ; R861.1 82.13,95.47 v2(82.15,95.5) ; v2(83.58,98.62) 83.47,98.52 C451.1
  BOTTOM w0.381: 110.6,25.72 110.6,26.18 109.67,27.11 109.22,27.11 108.91,27.41 108.91,27.87 108.62,28.16 C1251.1 ; v4(15.34,61.56) C497.1 15.78,60.8 15.86,60.72 16.37,60.72 U60.5 ; R866.1 20.13,58.84 19.87,58.59 18.03,58.59 v4(17.38,57.94) U58.5 15.95,57.94 C493.1 ; U55.5 C487.1 123.52,23.86 123.57,23.91 v4(123.57,24.48) C905.1 U114.5 ; U522.H8 111.43,21 v1(111.44,21) ; R816.2 v4(87.25,39.43) ; v4(80.84,47.94) 80.81,47.96 R91.1 ; U522.J6 v3(112.25,22.57) ; U533.5 C1297.1 v4(123.49,27.26) ; R187.2 R815.2 v4(87.26,42.47) ; U534.5 v4(121.54,17.83) ; C1295.1 v4(104.58,31.79) ; v4(84.77,39.73) 84.76,39.72 R158.2 R203.1 R873.2 ; R95.1 v4(80.9,52.95) ; R304.1 v4(124.37,21.23) ; R169.1 v2(80.76,54.88) ; R97.1 89.22,37.71 v4(88.82,38.1) ; C1249.1 107.35,27.22 108.27,26.3 v3(108.27,25.8) 108.26,25.8 U522.D3 ; v2(75.47,98.65) 75.62,98.49 C453.1 ; v4(101.05,64.97) 101.19,64.82 C1318.1 ; U522.G4 v3(110.65,25) ; U555.8 99.81,73.32 v4(99.45,73.68) ; R299.1 v4(124.58,16.72) ; R303.1 v4(117.74,23.16) ; R825.1 v4(125.14,29.18) ; R168.1 R171.1 ; v4(81.98,39.92) C297.1 ; R93.1 80.66,45.81 v4(80.77,45.69) ; R862.1 82.73,95.47 82.7,95.5 v2(82.15,95.5) ; R160.1 R172.1 ; R161.1 v4(88.05,44.79)
  BOTTOM w0.508: v4(84.73,42.67) 84.64,42.76 R204.1 R205.1 ; R172.1 v4(84.69,45.81) ; U62.5 46.81,64.22 v4(46.8,64.23) ; v5(33.49,70.5) 33.86,70.87 R656.1 ; v4(105.82,23.33) 104.81,23.33 104.68,23.21 104.02,23.21 R809.1 ; R157.1 v4(108.22,59) ; R143.1 v4(93.92,60.64) ; R171.1 v4(88.05,44.79) ; C1296.1 105.25,32.63 104.58,31.97 v4(104.58,31.79) 103.95,31.79 103.85,31.89 R811.1 ; R865.1 R866.1
  BOTTOM w0.889: 94.35,36.64 J11.2 ; J11.2 94.35,38.07 ; J11.2 95.06,37.36
  vias: v2(42.81,33.6) v2(42.81,32.81) v2(42.83,32.05) v2(42.89,31.23) v2(43.47,33.6) v2(43.47,32.81) v2(43.5,32.05) v2(43.55,31.23) v2(88.3,41.47) v4(14.69,85.27) v4(14.69,83.91) v4(14.7,82.5) v4(32.66,69.2) v4(33.35,69.2) v4(59.06,80.85) v4(59.07,80.02) v4(59.08,79.18) v4(59.13,78.33) v4(60.19,79.48) v4(60.2,78.62) v4(78.09,96.43) v4(79.19,95.33) v4(80.59,93.9) v4(81.51,93.16) v4(86.56,53.07) v4(97.08,62.03) v4(97.84,62.04) v7(23.28,78.75)
PEXM2_1_COEX1: length 20.1
  BOTTOM w0.137: TP130.1 35.8,51.25 24.4,51.25 21.88,48.73 J46.48
PEXM2_1_COEX2: length 20.4
  BOTTOM w0.137: J46.46 22.38,48.39 24.98,50.98 34.54,50.98 38.24,47.29 TP129.1
PEXM2_1_COEX3: length 21.5
  BOTTOM w0.137: J46.44 22.88,48.15 25.45,50.72 34.4,50.72 37.54,47.58 37.54,45.19 TP128.1
PEXM2_2_COEX1: length 14.1
  TOP w0.137: J52.48 v2(27.14,33.6)
  L3_INT_1 w0.107: v2(27.14,33.6) 28.58,32.16 36.55,32.16 37.44,31.28 38.2,31.28 38.3,31.37 TP141.1
PEXM2_2_COEX2: length 13.2
  TOP w0.137: v2(26.64,32.74) 26.64,33.27 26.64,33.28 J52.46
  L3_INT_1 w0.107: v2(26.64,32.74) 27.56,31.82 34.7,31.82 35.6,30.92 TP140.1
PEXM2_2_COEX3: length 17.8
  TOP w0.137: J52.44 v2(26.14,33.6)
  L3_INT_1 w0.107: TP139.1 34.2,30.17 32.99,31.38 27.41,31.38 26.14,32.66 v2(26.14,33.6)
PEXM2_CLKREQ: length 4
  TOP w0.137: R798.2 R668.2 20.87,51.72 20.87,52.69 20.63,52.92 v2(20.63,53.41)
  BOTTOM w0.137: J46.53 v2(20.63,53.41)
PEXM2_CLKREQ2: length 13.9
  TOP w0.137: R805.2 38.36,38.39 38.44,38.47 R806.2 37.67,38.98 v2(37.43,39.21) ; J52.53 v2(28.39,40.45)
  L3_INT_1 w0.107: v2(37.43,39.21) 36.2,40.45 v2(28.39,40.45)
PEXM2_LED1: length 4.9
  BOTTOM w0.137: D510.C 32.84,45.89 32.38,46.35 J46.6
PEXM2_LED2: length 28.5
  TOP w0.137: v4(16.65,33.63) 16.64,33.63 J52.6 ; D511.C 41.59,32 41.01,31.42 v2(40.11,31.42)
  L3_INT_1 w0.107: v4(16.65,33.63) 16.95,33.93 16.97,33.93 17.05,34.01 27.31,34.01 28.77,32.55 38.98,32.55 v2(40.11,31.42)
PEXM2_PET1_N: length 2.5
  BOTTOM w0.124: C1168.1 24.56,56.99 arc(24.68,56.8) 24.73,56.58 24.73,54.83 arc(24.7,54.71) J46.37
PEXM2_PET1_P: length 2.5
  BOTTOM w0.124: C1166.1 25.22,56.99 arc(25.09,56.8) 25.05,56.58 25.05,54.81 arc(25.07,54.7) J46.35
PEXM2_PET2_N: length 1.6
  TOP w0.124: C1294.1 24.4,43.84 arc(24.33,43.73) 24.3,43.6 24.3,42.65 arc(24.32,42.53) J52.37
PEXM2_PET2_P: length 1.6
  TOP w0.124: C1293.1 23.88,43.84 arc(23.96,43.73) 23.98,43.6 23.98,42.65 arc(23.96,42.53) J52.35
PEXM2_WAKE2_B: length 12.3
  TOP w0.137: J52.55 v2(28.89,39.78) ; R804.2 v2(37.2,38.63)
  L3_INT_1 w0.107: v2(28.89,39.78) 36.04,39.78 v2(37.2,38.63)
PEXM2_WAKE_B: length 2.9
  TOP w0.137: v2(20.13,52.79) 20.13,52.36 20.01,52.23 R667.2
  BOTTOM w0.137: J46.55 v2(20.13,52.79)
PMIC_EN: length 2.9
  TOP w0.254: U561.22 71.1,71.01 R927.2
PMIC_FSOB: length 3.8
  TOP w0.254: R936.2 75.3,71.35 75.14,71.51 75.14,74.01 74.89,74.26 U561.29
PMIC_INT_B: length 32.3
  TOP w0.137: v3(68.63,53.39) 68.62,53.39 U14.K5
  TOP w0.254: v4(72.34,71.51) 72.1,71.74 U561.24
  L3_INT_1 w0.107: v2(65.66,71.6) 66.01,71.95 71.89,71.95 v4(72.34,71.51)
  BOTTOM w0.137: v3(68.63,53.39) 68.23,53.8 68.23,55.96 70.74,58.48 70.74,66.74 66.69,70.79 66.69,71.01 66.1,71.6 v2(65.66,71.6) ; R929.2 72.25,71.42 v4(72.34,71.51)
PMIC_LICELL: length 2.3
  TOP w0.254: U561.46 72.6,82.38 72.25,82.73 C1546.1
PMIC_POR_B: length 5
  TOP w0.254: U561.42 75.12,80.76 75.49,81.14 75.49,82.32 76.48,83.3 R939.1 R928.2
PMIC_RESET_MCU_B: length 3.7
  TOP w0.254: R934.2 v4(70.47,71.52) 70.47,72 70.6,72.13 U561.21
  BOTTOM w0.254: v4(70.47,71.52) R934.2
PMIC_STBY: length 3.1
  TOP w0.254: R930.1 71.6,71.38 U561.23
PMIC_V1P5A: length 9.5
  TOP w0.254: U561.41 75.62,80.26 76.29,80.93 v4(76.29,82.39) C1540.1 ; R937.1 v4(73.52,85.44)
  L4_INT_2 w0.254: v4(73.52,85.44) 74.41,85.44 76.29,83.56 v4(76.29,82.39)
PMIC_V1P5D: length 3.3
  TOP w0.254: U561.40 75.87,79.76 77.05,80.94 C1545.1
PMIC_VDDOTP: length 2.2
  TOP w0.254: R933.1 69.07,82.54 69.1,82.52 U561.53
PORESET_B: length 250.8
  TOP w0.137: v2(120.95,28.24) 120.67,28.52 119.4,28.52 114.38,33.54 108.26,33.54 105.24,30.52 U532.3 ; v2(17.87,65.26) 17.87,63.67 18.63,62.9 18.63,60.69 v2(17.87,59.93) ; v2(121.37,20.59) R301.2 119.98,19.2 U54.C2 ; U56.2 121.96,25.76 121.47,25.26 v2(121.47,23.6)
  L3_INT_1 w0.107: v2(104.1,80.53) 104.1,81.47 102.23,83.35 102.23,84.85 101.34,85.74 93.18,85.74 v2(89.63,89.29) ; v2(105.58,58.72) 102.67,58.72 101.96,59.43 96.23,59.43 94.19,61.47 94.07,61.47 93.93,61.61 91.69,61.61 91.05,62.25 87.85,62.25 87.5,61.9 86.29,61.9 85.68,61.28 84.77,61.28 84.32,61.73 77.75,61.73 73.88,57.87 73.7,57.87 73.32,57.49 64.63,57.49 63.38,58.74 57.26,58.74 57.07,58.93 56.74,58.93 56.5,58.69 56.5,58.38 56.06,57.94 53.99,57.94 53.55,58.39 50.79,58.39 50.13,59.05 49.74,59.05 49.35,58.66 46.36,58.66 v2(46.13,58.89) 43.22,58.89 41.58,60.53 36.91,60.53 34.31,63.13 32.53,63.13 30.52,65.15 29.43,65.15 27.94,66.63 19.24,66.63 v2(17.87,65.26) ; v2(120.95,28.24) 121.5,27.69 121.5,23.64 v2(121.47,23.6) 121.47,22.81 121.37,22.72 v2(121.37,20.59)
  L4_INT_2 w0.107: v2(104.1,80.53) 104.1,77.75 105.35,76.5 105.35,67.51 105.76,67.1 105.76,66.2 105.82,66.13 105.82,62.07 105.87,62.02 105.87,59.01 v2(105.58,58.72) 105.29,58.44 105.18,58.44 102.52,55.78 102.52,50.67 101.06,49.2 101.06,45.33 103.33,43.05 103.82,43.05 105.75,41.11 105.75,39.44 110.78,34.41 110.87,34.41 114.66,30.62 v2(114.66,30.21)
  BOTTOM w0.137: U55.3 121.44,23.63 v2(121.47,23.6) ; U58.2 15.9,57.29 14.84,58.35 14.84,60.09 15.1,60.34 15.57,60.34 15.99,59.93 v2(17.87,59.93) 17.85,59.91 U60.2 ; v2(114.66,30.21) 117.28,30.21 118.97,28.52 U533.2 120.67,28.52 v2(120.95,28.24) ; U62.2 43.66,64.87 42.18,63.4 42.18,61.73 45.03,58.89 v2(46.13,58.89) 46.14,58.89 46.44,59.19 46.44,60.87 46.5,60.93 46.5,61.5 46.13,61.87 U546.2 ; U527.2 v2(89.63,89.29)
PROG_SFP_EN: length 10.8
  TOP w0.137: R409.2 90.76,66.18 90.89,66.06 U566.2 92.09,66.06 92.8,65.34 92.8,64.81 94.48,63.14 97.14,63.14 97.27,63.26 97.7,63.26 98.26,63.82 U549.3
PROG_SFP_Y_EN: length 8.3
  TOP w0.305: R409.1 90.16,65.16 89.32,65.16 88.49,64.32 88.49,59.25 Q3.1
PS_3V3_PG: length 20.4
  TOP w0.254: U560.23 117.98,72.02 v4(117.74,72.26)
  L3_INT_1 w0.107: v4(117.74,72.26) 116.4,73.6 v2(111.62,73.6)
  L4_INT_2 w0.107: v4(117.74,72.26) 117.74,78.84 119.19,80.29 119.19,81.36 v2(118.9,81.64)
  BOTTOM w0.137: v2(118.9,81.64) 118.45,81.64 118.27,81.82 R6.1 ; v2(111.62,73.6) 111.62,73.11 R901.2
PS_5V0_EN: length 4.6
  TOP w0.137: U1.11 113.77,81.68 v2(114.03,81.42)
  BOTTOM w0.137: v2(114.03,81.42) 116.24,81.42 R5.2 116.74,80.96 R6.2
PS_V5V0_PG: length 67.2
  TOP w0.137: v2(126.78,28.2) 125.88,28.2 125.1,27.42 123.97,27.42 123.53,27.87 U562.1 ; v2(116,80.97) 116.04,80.97 116.04,80.97 R10.2 116.26,81.43 114.8,81.43 114.27,81.95 U1.12
  L3_INT_1 w0.107: v2(126.78,28.2) 126.81,28.24 126.81,29.5 126.71,29.61 126.71,33.37 125.91,34.17 125.91,50.3 120.77,55.43 120.77,58.43 115.81,63.4 v2(115.81,65.04)
  L4_INT_2 w0.107: v2(116,80.97) 115.35,80.32 115.35,75.01 116.47,73.89 116.47,65.7 v2(115.81,65.04)
PS_VDD_EN: length 82.5
  TOP w0.137: U557.B2 v3(121.75,46.96)
  TOP w0.254: C1551.1 v4(74.38,71.49) 74.38,72 74.43,72.04 74.43,72.94 74.1,73.27 U561.28
  L3_INT_1 w0.107: v2(119.7,76.22) 119.06,75.58 103.06,75.58 102.17,74.69 99.8,74.69 99.19,74.08 94.86,74.08 93.91,73.13 81.55,73.13 79.03,70.62 75.25,70.62 v4(74.38,71.49)
  L4_INT_2 w0.107: v3(121.75,46.96) 122.85,48.06 122.85,61.76 119.7,64.91 v2(119.7,76.22)
PS_VDD_PG: length 38.4
  TOP w0.137: U562.2 125.38,28.52 125.6,28.73 v2(125.63,28.73)
  TOP w0.254: v4(123.34,50.23) 123.34,47.75 U557.A2
  L3_INT_1 w0.107: v2(125.63,28.73) 125.63,29.3 125.32,29.61 125.08,29.61 123.85,30.83 123.85,34.45 122.69,35.62 122.69,42.14 121.37,43.46 121.37,47.09 123.34,49.06 v4(123.34,50.23)
  BOTTOM w0.137: R66.2 125.26,50.23 v4(123.34,50.23)
PWR_PROG_MTR: length 33.1
  TOP w0.137: v1(71.83,46.99) 71.43,46.6 U14.F13
  L3_INT_1 w0.254: 82.26,46.78 82.52,46.53 82.52,45.56 84.67,43.41 85.04,43.41 85.04,43.41 90.5,43.41 93.13,40.77 93.13,38.21 93.08,38.16 J11.1
  L3_INT_1 w0.305: 82.26,46.78 76.18,46.78 74.98,45.59 71.39,45.59 71.12,45.85 71.12,46.29 v1(71.83,46.99)
  BOTTOM w0.381: J11.1 92.21,37.36 92.09,37.23 R100.1
PWR_PROG_SFP: length 67.7
  TOP w0.137: U14.G13 70.63,46.6 v3(71.03,46.99)
  TOP w0.305: Q3.2 86.24,60.31 85.57,60.99 v2(85.57,61.76)
  L3_INT_1 w0.152: 74.54,48.21 71.71,48.21 71.44,47.95 71.44,47.41 v3(71.03,46.99)
  L3_INT_1 w0.305: v2(81.62,48.93) 81.18,49.37 80.62,49.37 79.58,48.34 74.66,48.34 74.54,48.21 ; v2(84.6,59.7) 85.14,59.7 85.24,59.8 90.31,59.8 90.61,59.5 90.75,59.5 91.04,59.2 91.75,59.2 v2(92.14,58.81)
  L4_INT_2 w0.305: v2(92.14,58.81) 91.78,58.45 91.78,57.59 92.09,57.27 92.09,55.4 92.63,54.87 92.63,51.57 91.63,50.57 87.23,50.57 86.29,49.63 86.29,48.22 85.65,47.58 84.24,47.58 82.9,48.93 v2(81.62,48.93)
  BOTTOM w0.305: v2(84.6,59.7) 84.6,59.1 84.7,59 C329.1 85.45,59.06 R101.1 85.45,60.93 85.57,61.05 v2(85.57,61.76) 88.02,61.76 89.58,63.32 89.58,67.13 92.2,69.74 93.38,69.74 94.07,69.06 96.02,69.06 J74.2
QSG0_LED0: length 53.2
  TOP w0.137: v2(65.01,113.43) R645.1 ; v6(39.14,77.89) 39.08,77.89 39.07,77.9 U123.E2
  L3_INT_1 w0.107: v6(39.14,77.89) 39.29,78.05 43.73,78.05 44.64,78.95 44.99,78.95 45.07,78.88 47.81,78.88 49.9,80.97 51.1,80.97 53.58,83.45 53.58,85.54 58.44,90.4 58.44,92.17 61.78,95.52 61.78,98.11 64.37,100.7 64.37,112.79 v2(65.01,113.43)
QSG0_LED1: length 60.7
  TOP w0.137: U123.D1 37.58,79.26 v2(37.58,79.37) ; v2(43.8,109.11) R646.1
  L3_INT_1 w0.107: v2(43.8,109.11) 43.39,108.7 38.85,108.7 38.77,108.78 30.72,108.78 30.17,108.22 30.17,107.09 29.4,106.32 25.8,106.32 21.06,101.58 21.06,90.7 26.68,85.08 30.74,85.08 31.46,84.37 33.62,84.37 37.58,80.41 v2(37.58,79.37)
QSG0_MDI0_N: length 26.4
  TOP w0.105: v2(45.93,79.52) 45.93,79.52 45.46,79.52 45.03,79.95 U123.D30
  L3_INT_1 w0.094: P1.21 58.96,94.34 58.96,94.13 58.69,93.86 58.69,93.73 58.88,93.54 58.88,93.4 58.75,93.27 58.62,93.27 58.43,93.46 58.29,93.46 58.16,93.33 58.16,93.2 58.35,93 58.35,92.87 58.22,92.74 58.09,92.74 57.89,92.93 57.76,92.93 53.69,88.86 53.37,88.86 51.68,87.17 51.68,84.33 47.48,80.14 45.17,80.14 45.08,80.04 45.08,79.66 45.22,79.52 v2(45.93,79.52)
QSG0_MDI0_P: length 26.5
  TOP w0.105: v2(43.76,80.06) 43.78,80.04 43.8,80.04 43.89,79.95 U123.D31
  L3_INT_1 w0.094: v2(43.76,80.06) 44.06,79.76 44.47,79.76 44.71,80 44.71,80.2 45.02,80.51 47.33,80.51 51.3,84.48 51.3,87.32 53.22,89.23 53.54,89.23 58.58,94.27 P1.15
QSG0_MDI1_N: length 22
  TOP w0.105: v2(46.47,81.15) 46.42,81.15 U123.C24
  L3_INT_1 w0.094: P1.16 56.58,93.65 52.76,89.84 51.88,89.84 49.56,87.51 49.56,85.16 46.36,81.96 46.36,81.26 v2(46.47,81.15)
QSG0_MDI1_P: length 22
  TOP w0.105: v2(45.76,81.2) 45.76,81.14 U123.C25
  L3_INT_1 w0.094: P1.23 55.58,93.18 54.96,92.56 54.83,92.56 54.39,93 54.26,93 54.12,92.87 54.12,92.73 54.56,92.29 54.56,92.16 54.43,92.03 54.3,92.03 53.86,92.47 53.72,92.47 53.59,92.34 53.59,92.2 54.03,91.76 54.03,91.63 52.61,90.21 51.73,90.21 49.18,87.66 49.18,85.31 45.99,82.11 45.99,81.43 v2(45.76,81.2)
QSG0_MDI2_N: length 22.9
  TOP w0.094: 47.74,81.34 47.65,81.26 47.61,81.26 46.75,80.4 46.75,80.36 46.62,80.23 U123.C23
  TOP w0.124: 47.74,81.34 47.85,81.46 47.85,81.46 47.99,81.6 47.99,84.75 v2(48.22,84.98)
  L3_INT_1 w0.094: v2(48.22,84.98) 47.95,85.25 47.95,91.93 49.06,93.04 50.13,93.04 50.22,92.95 50.22,92.37 50.32,92.28 50.51,92.28 50.6,92.37 50.6,92.95 50.69,93.04 50.88,93.04 50.98,92.95 50.98,92.37 51.07,92.28 51.26,92.28 51.35,92.37 51.35,92.95 51.45,93.04 52.58,93.04 53.58,94.05 P1.24
QSG0_MDI2_P: length 23
  TOP w0.094: U123.D29 45.93,79.95 46.46,80.48 46.46,80.52 47.49,81.55 47.49,81.55 47.51,81.57
  TOP w0.124: v2(47.31,84.98) 47.65,84.64 47.65,81.71 47.53,81.59 47.53,81.59 47.51,81.57
  L3_INT_1 w0.094: v2(47.31,84.98) 47.58,85.25 47.58,92.08 48.91,93.41 52.39,93.41 52.58,93.61 P1.18
QSG0_MDI3_N: length 20.7
  TOP w0.124: P1.19 50.58,90.2 49.41,89.04 49.41,81.34 47.41,79.33 47.14,79.33 46.95,79.15 46.95,78.88 U123.C21
QSG0_MDI3_P: length 20.7
  TOP w0.124: U123.C22 46.62,79.23 46.62,79.23 46.62,79.28 47,79.66 47.27,79.66 49.09,81.48 49.09,89.17 50.26,90.34 50.26,92.24 50.13,92.36 49.5,92.36 49.37,92.49 49.37,92.73 49.5,92.86 50.13,92.86 50.26,92.98 50.26,93.23 50.13,93.36 49.5,93.36 49.37,93.48 49.37,93.73 49.5,93.85 50.13,93.85 50.26,93.98 50.26,94.27 P1.26
QSG1_LED0: length 36.2
  TOP w0.137: R643.1 63.4,87.39 56.68,87.39 v2(55.53,88.54) ; v2(36.66,79.22) 37.12,79.22 37.65,78.69 37.65,78.35 37.32,78.01 U123.C3
  L3_INT_1 w0.107: v2(36.66,79.22) 37.82,78.05 38.72,78.05 38.97,78.3 39.18,78.3 39.53,78.66 39.53,78.89 39.85,79.21 45.1,79.21 45.2,79.11 46.88,79.11 52.28,84.51 52.28,86.36 54.46,88.54 v2(55.53,88.54)
QSG1_LED1: length 18.7
  TOP w0.137: U123.B2 35.95,78.28 v2(35.95,81.17) ; R644.1 v2(46.47,86.83)
  L4_INT_2 w0.107: v2(35.95,81.17) 35.95,82.84 39.9,86.78 46,86.78 46.06,86.83 v2(46.47,86.83)
QSG1_MDI0_N: length 30.1
  TOP w0.124: U123.B17 42.94,81.25 42.96,81.25 43.34,81.63 43.34,81.65 43.39,81.7 43.39,85.92 44.22,86.75 44.22,97.04 48.92,101.74 48.92,102.68 49.05,102.8 49.76,102.8 49.88,102.92 49.88,103.17 49.76,103.3 49.05,103.3 48.92,103.42 48.92,103.67 49.05,103.8 49.76,103.8 49.88,103.92 49.88,104.17 49.76,104.29 49.05,104.29 48.92,104.42 48.92,104.71 P1.13
QSG1_MDI0_P: length 30.2
  TOP w0.124: U123.B18 42.29,81.31 42.55,81.57 42.77,81.57 42.78,81.58 42.82,81.58 43.01,81.77 43.01,81.78 43.06,81.83 43.06,86.06 43.9,86.89 43.9,97.17 48.6,101.87 48.6,105.93 P1.6
QSG1_MDI1_N: length 51.3
  TOP w0.105: v2(43.1,79.94) 43.27,80.11 U123.C28
  L3_INT_1 w0.094: P1.5 52.58,107.03 52.67,106.94 60.59,106.94 62.08,105.45 62.08,103.24 59.83,100.99 49.54,100.99 44.36,95.81 44.36,82.35 42.96,80.94 42.96,80.08 v2(43.1,79.94)
QSG1_MDI1_P: length 51.2
  TOP w0.105: U123.C29 42.62,80.21 v2(42.39,79.98)
  L3_INT_1 w0.094: v2(42.39,79.98) 42.59,80.18 42.59,81.1 43.99,82.5 43.99,95.96 49.39,101.36 59.68,101.36 61.71,103.4 61.71,105.3 60.44,106.57 52.75,106.57 52.66,106.48 52.66,106.29 P1.11
QSG1_MDI2_N: length 35.4
  TOP w0.124: U123.B15 44.24,85.31 45.09,86.17 45.09,96.64 48.35,99.89 54.26,99.89 54.92,100.55 54.92,102.5 55.04,102.63 55.72,102.63 55.85,102.75 55.85,103 55.72,103.12 55.04,103.12 54.92,103.25 54.92,103.5 55.04,103.62 55.72,103.62 55.85,103.75 55.85,103.99 55.72,104.12 55.04,104.12 54.92,104.24 54.92,104.7 P1.10
QSG1_MDI2_P: length 35.5
  TOP w0.124: U123.B16 43.91,81.57 43.91,85.45 44.77,86.3 44.77,96.78 48.2,100.21 54.13,100.21 54.6,100.68 54.6,105.92 P1.3
QSG1_MDI3_N: length 40.9
  TOP w0.124: U123.C26 44.99,81.02 44.99,84.95 45.85,85.81 45.85,96.13 48.5,98.79 59.13,98.79 60.47,100.13 60.47,105.73 60.46,105.75 60.46,106.02 P1.2
QSG1_MDI3_P: length 40.9
  TOP w0.124: U123.C27 44.16,80.84 44.34,80.84 44.43,80.93 44.44,80.93 44.66,81.16 44.66,85.09 45.52,85.95 45.52,96.27 45.62,96.37 45.63,96.37 48.37,99.11 59,99.11 60.15,100.26 60.15,100.82 60.03,100.95 59.66,100.95 59.54,101.07 59.54,101.32 59.66,101.45 60.03,101.45 60.15,101.57 60.15,101.82 60.03,101.94 59.66,101.94 59.54,102.07 59.54,102.32 59.66,102.44 60.03,102.44 60.15,102.57 60.15,102.81 60.03,102.94 59.66,102.94 59.54,103.06 59.54,103.31 59.66,103.44 60.03,103.44 60.15,103.56 60.15,103.9 59.58,104.48 P1.8
QSG2_LED0: length 62.2
  TOP w0.137: v2(41.9,109.11) R647.1 ; U123.C5 36.8,77.12 35.85,77.12 v2(35.55,76.82)
  L3_INT_1 w0.107: v2(35.55,76.82) 35.55,80.59 33.57,82.56 32.35,82.56 30.9,84.01 27.26,84.01 23.01,88.26 21.62,88.26 20.83,89.05 20.83,101.68 25.98,106.82 27.7,106.82 28.38,107.49 28.38,108.43 29.05,109.11 v2(41.9,109.11)
QSG2_LED1: length 51
  TOP w0.137: v2(37.32,75.96) 37.66,75.96 U123.D5 ; R648.1 v2(20.56,113.71)
  L3_INT_1 w0.107: v2(20.56,113.71) 20.56,88.99 21.67,87.87 22.43,87.87 22.86,87.45 22.86,86.79 27.49,82.16 30.95,82.16 31.61,81.5 33.7,81.5 35.17,80.03 35.17,77.72 35.14,77.69 35.14,76.65 35.82,75.96 v2(37.32,75.96)
QSG2_MDI0_N: length 20.3
  TOP w0.124: U123.C32 40.67,80.61 40.36,80.92 40.23,80.92 40.22,80.92 40.16,80.92 40.15,80.93 40.02,80.93 39.94,81.01 39.94,81.25 39.52,81.67 39.52,81.68 39.42,81.77 39.42,85.61 40.57,86.76 40.57,86.78 40.78,86.99 40.78,87.99 v2(41.06,88.27)
  L3_INT_1 w0.094: v2(41.06,88.27) 40.79,88.54 40.79,89.4 39.09,91.1 39.09,91.23 39.21,91.34 39.21,91.48 39.08,91.61 38.94,91.61 38.83,91.49 38.69,91.49 38.56,91.63 38.56,91.76 38.68,91.88 38.68,92.01 38.54,92.14 38.41,92.14 38.3,92.03 38.16,92.03 38.03,92.16 38.03,92.29 38.15,92.41 38.15,92.54 38.01,92.67 37.88,92.67 37.76,92.56 37.63,92.56 37.5,92.69 37.5,92.82 37.61,92.94 37.61,93.07 37.48,93.21 37.35,93.21 37.23,93.09 37.1,93.09 36.97,93.22 36.97,93.36 37.08,93.47 37.08,93.61 36.95,93.74 36.82,93.74 36.7,93.62 36.57,93.62 36.08,94.1 36.08,94.75 P2.21
QSG2_MDI0_P: length 20.3
  TOP w0.124: v2(40.15,88.27) 40.45,87.97 40.45,87.12 40.24,86.91 40.24,86.9 39.09,85.75 39.09,81.64 39.19,81.54 39.19,81.53 39.61,81.12 39.61,80.84 39.85,80.6 U123.C33
  L3_INT_1 w0.094: P2.15 35.29,94.38 40.42,89.25 40.42,88.54 v2(40.15,88.27)
QSG2_MDI1_N: length 24.2
  TOP w0.124: v2(41.23,85.6) 40.93,85.29 40.93,84.89 40.92,84.88 40.92,84.73 40.12,83.93 40.12,82.9 40.21,82.81 40.21,81.83 40.46,81.58 40.58,81.58 40.92,81.25 U123.B19
  L3_INT_1 w0.094: v2(41.23,85.6) 40.96,85.87 40.96,86.7 40.25,87.41 36.51,87.41 34.33,89.59 32.92,89.59 32.44,90.08 32.44,93.49 33.29,94.34 P2.16
QSG2_MDI1_P: length 24.1
  TOP w0.124: v2(40.32,85.6) 40.6,85.32 40.6,84.86 39.8,84.06 39.8,82.77 39.89,82.67 39.89,81.69 40.32,81.26 40.33,81.26 U123.B20
  L3_INT_1 w0.094: v2(40.32,85.6) 40.59,85.87 40.59,86.55 40.1,87.04 36.36,87.04 34.17,89.22 32.77,89.22 32.07,89.93 32.07,90.45 31.97,90.54 31.3,90.54 31.21,90.63 31.21,90.82 31.3,90.92 31.97,90.92 32.07,91.01 32.07,91.2 31.97,91.29 31.3,91.29 31.21,91.39 31.21,91.57 31.3,91.67 31.97,91.67 32.07,91.76 32.07,93.85 32.29,94.08 P2.23
QSG2_MDI2_N: length 23.7
  TOP w0.124: v2(41.45,83.08) 41.37,83.08 41.2,82.91 41.2,82.73 41.32,82.61 U123.A9
  L3_INT_1 w0.094: v2(41.45,83.08) 41.18,83.34 41.18,83.95 40.53,84.59 37.91,84.59 34.05,88.45 31.58,88.45 30.45,89.58 30.45,92.13 30.55,92.22 31.14,92.22 31.24,92.31 31.24,92.5 31.14,92.6 30.55,92.6 30.45,92.69 30.45,92.88 30.55,92.97 31.14,92.97 31.24,93.07 31.24,93.25 31.14,93.35 30.55,93.35 30.45,93.44 30.45,93.71 30.08,94.08 30.08,94.75 P2.24
QSG2_MDI2_P: length 23.9
  TOP w0.124: U123.A10 40.67,82.46 40.85,82.64 40.85,82.77 v2(40.54,83.08)
  L3_INT_1 w0.094: P2.18 29.65,97.12 29.65,95.55 29.41,95.31 29.41,94.59 29.65,94.35 29.65,93.84 30.08,93.41 30.08,89.43 31.43,88.08 33.89,88.08 37.75,84.22 40.38,84.22 40.81,83.79 40.81,83.34 v2(40.54,83.08)
QSG2_MDI3_N: length 32.3
  TOP w0.105: U123.C30 41.97,80.32 v2(41.68,80.03)
  L3_INT_1 w0.094: v2(41.68,80.03) 41.3,80.41 40.04,80.41 33.46,86.99 27.08,86.99 23.81,90.26 23.81,95.42 24.85,96.46 26.26,96.46 P2.19
QSG2_MDI3_P: length 32.2
  TOP w0.105: v2(41.62,81.22) 41.62,81.22 41.62,81.21 41.32,80.91 U123.C31
  L3_INT_1 w0.094: P2.26 26.29,95.84 26.04,96.09 25.01,96.09 24.18,95.27 24.18,94.84 24.28,94.75 24.45,94.75 24.55,94.65 24.55,94.46 24.45,94.37 24.28,94.37 24.18,94.28 24.18,94.09 24.28,93.99 24.45,93.99 24.55,93.9 24.55,93.71 24.45,93.62 24.28,93.62 24.18,93.52 24.18,93.34 24.28,93.24 24.45,93.24 24.55,93.15 24.55,92.96 24.45,92.87 24.28,92.87 24.18,92.77 24.18,90.42 27.23,87.37 33.61,87.37 40.2,80.78 41.18,80.78 v2(41.62,81.22)
QSG3_LED0: length 13.9
  TOP w0.137: U123.B4 36.12,76.17 35.59,76.17 35.12,76.64 35.12,77.55 35.47,77.89 35.47,87.57 36.05,88.16
QSG3_LED1: length 22.5
  TOP w0.094: 35.8,75.71 36.13,75.71 36.54,75.3 U123.C6
  TOP w0.137: R650.1 v2(22.34,87.14) ; 35.8,75.71 v2(35.42,75.71)
  L3_INT_1 w0.107: v2(22.34,87.14) 22.34,86.25 24.75,83.83 25.14,83.83 27.89,81.09 32.36,81.09 34.9,78.54 34.9,76.22 v2(35.42,75.71)
QSG3_MDI0_N: length 39.1
  TOP w0.124: P2.13 26.71,104.94 26.71,104.47 26.58,104.35 26.11,104.35 25.99,104.22 25.99,103.97 26.11,103.85 26.58,103.85 26.71,103.72 26.71,103.48 26.58,103.35 26.11,103.35 25.99,103.23 25.99,102.98 26.11,102.85 26.58,102.85 26.71,102.73 26.71,102.48 26.58,102.35 26.11,102.35 25.99,102.23 25.99,101.98 26.11,101.86 26.58,101.86 26.71,101.73 26.71,101.34 28.98,99.07 37.09,99.07 38.55,97.61 38.55,89.55 38.11,89.11 38.11,88.37 36.75,87.01 36.75,81.3 36.75,81.29 36.75,81.27 U123.C36
QSG3_MDI0_P: length 39
  TOP w0.124: P2.6 27.29,105.1 27.03,104.84 27.03,101.47 29.11,99.39 37.22,99.39 38.87,97.74 38.87,89.42 38.43,88.98 38.43,88.24 37.07,86.88 37.07,81.43 37.75,80.75 37.75,80.28 U123.C1
QSG3_MDI1_N: length 38
  TOP w0.124: U123.D34 38.71,79.62 38.09,79.62 37.96,79.75 37.96,80.1 38.03,80.17 38.03,80.87 37.99,80.9 37.99,80.91 37.43,81.47 37.43,86.43 38.76,87.76 38.76,88.84 39.2,89.28 39.2,98.04 36.71,100.54 30.77,100.54 29.4,101.91 29.4,106.9 29.29,107.01 P2.5
QSG3_MDI1_P: length 38
  TOP w0.124: P2.11 29.72,104.79 29.72,104.16 29.84,104.04 30.69,104.04 30.81,103.92 30.81,103.67 30.69,103.54 29.84,103.54 29.72,103.42 29.72,103.17 29.84,103.04 30.69,103.04 30.81,102.92 30.81,102.67 30.69,102.55 29.84,102.55 29.72,102.42 29.72,102.04 30.9,100.86 36.84,100.86 39.52,98.18 39.52,89.15 39.08,88.71 39.08,87.63 37.75,86.3 37.75,81.6 38.31,81.04 38.31,81.03 38.35,81 38.35,80.05 38.39,80 U123.D35
QSG3_MDI2_N: length 34.9
  TOP w0.124: P2.10 31.72,104.79 31.72,102.94 32.54,102.12 33.11,102.12 33.24,102.24 33.24,102.63 33.36,102.76 33.61,102.76 33.73,102.63 33.73,102.24 33.86,102.12 34.11,102.12 34.23,102.24 34.23,102.63 34.36,102.76 34.6,102.76 34.73,102.63 34.73,102.24 34.85,102.12 35.1,102.12 35.23,102.24 35.23,102.63 35.35,102.76 35.6,102.76 35.72,102.63 35.72,102.24 35.85,102.12 36.56,102.12 40.26,98.42 40.26,88.97 39.73,88.44 39.73,87.23 38.56,86.06 38.56,81.75 39.12,81.19 39.12,80.84 U123.C34
QSG3_MDI2_P: length 34.9
  TOP w0.124: P2.3 31.4,106.01 31.4,102.8 32.41,101.8 36.42,101.8 39.94,98.28 39.94,89.11 39.41,88.58 39.41,87.37 38.24,86.2 38.24,81.61 38.72,81.13 U123.C35
